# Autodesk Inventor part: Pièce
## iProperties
Author: ajt
Created: 2001-10
Part Number: Pièce
Material: Par défaut
Document SubType Name: Modélisation
Designer: ajt
Control State: 0
Master: False
Checked Out: False
PropertySet Name: Design Tracking Control
Shininess: 21.0
PropertySet Name: _Private Model Information
Length Units: 11269
Angle Units: 11283
Time Units: 11279
Mass Units: 11290
Length Display Precision: 3
Angle Display Precision: 2
Compacted: False
Density: 0.0
Volumn: 0.0
Area: 0.0
PropertySet Name: Model Information
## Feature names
1. Extrusion1
